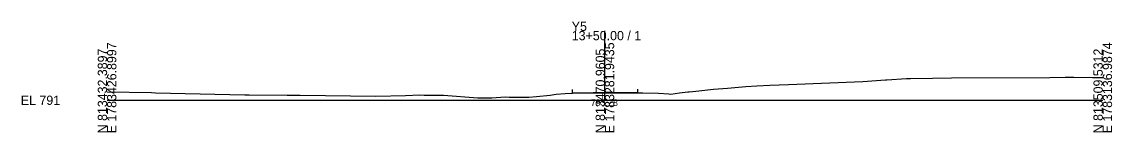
# Model space of a CAD drawing. Extents: x -26 to 1603, y -10 to 6526.
# Drawn here: x 1274.3 to 1602.8, y 490.3 to 523.7 of the extents above; entities that cross this region are included whole.
import ezdxf

# ---------------------------------------------------------------- set-up
doc = ezdxf.new("R2010")
doc.units = 0
for name, color, linetype in [('Exist Cross Section Cell', 7, 'Continuous'), ('Exist XS Center Line Elevation Label', 7, 'Continuous'), ('Exist XS Ground Line', 7, 'Continuous'), ('Prop XS EOT Tick Mark', 7, 'Continuous'), ('Prop XS Finish Grade Pavement', 7, 'Continuous')]:
    doc.layers.add(name, color=color, linetype=linetype)

msp = doc.modelspace()

# ---------------------------------------------------------------- linework, layer by layer
at = {"layer": 'Exist Cross Section Cell'}
for p, q in [((1450, 500), (1450, 520.95)), ((1300, 500), (1450, 500)), ((1450, 500), (1600, 500))]:
    msp.add_line(p, q, dxfattribs=at)
at = {"layer": 'Exist XS Ground Line'}
for p, q in [((1527.7, 505.7), (1534.55, 506.19)), ((1534.55, 506.19), (1534.91, 506.21)), ((1534.91, 506.21), (1540.91, 506.59)), ((1540.91, 506.59), (1542.07, 506.62)), ((1542.07, 506.62), (1548.73, 506.67)), ((1548.73, 506.67), (1554.42, 506.75)), ((1554.42, 506.75), (1584.03, 506.91)), ((1584.03, 506.91), (1588.69, 506.98)), ((1588.69, 506.98), (1591.33, 506.94)), ((1591.33, 506.94), (1596.88, 506.87)), ((1596.88, 506.87), (1600, 506.92)), ((1475.36, 502.52), (1477.42, 502.73)), ((1477.42, 502.73), (1482.76, 503.31)), ((1482.76, 503.31), (1486.98, 503.65)), ((1486.98, 503.65), (1492.47, 504.14)), ((1492.47, 504.14), (1495.81, 504.31)), ((1495.81, 504.31), (1499.65, 504.51)), ((1499.65, 504.51), (1505.3, 504.8)), ((1505.3, 504.8), (1527.7, 505.7)), ((1300, 502.5), (1313.35, 502.33)), ((1313.35, 502.33), (1314.59, 502.27)), ((1314.59, 502.27), (1336.94, 501.72)), ((1336.94, 501.72), (1341.48, 501.66)), ((1341.48, 501.66), (1342.85, 501.67)), ((1342.85, 501.67), (1354.29, 501.51)), ((1354.29, 501.51), (1358.18, 501.53)), ((1358.18, 501.53), (1381.01, 501.27)), ((1381.01, 501.27), (1389.89, 501.42)), ((1389.89, 501.42), (1394.24, 501.59)), ((1394.24, 501.59), (1395.53, 501.54)), ((1395.53, 501.54), (1401.38, 501.57)), ((1401.38, 501.57), (1411.71, 500.72)), ((1411.71, 500.72), (1413.49, 500.7)), ((1413.49, 500.7), (1415.96, 500.75)), ((1415.96, 500.75), (1419.99, 501.02)), ((1419.99, 501.02), (1421.1, 500.92)), ((1421.1, 500.92), (1422.36, 500.96)), ((1422.36, 500.96), (1427.06, 500.89)), ((1427.06, 500.89), (1429.41, 501.14)), ((1429.41, 501.14), (1433.5, 501.56)), ((1433.5, 501.56), (1435.29, 501.83)), ((1435.29, 501.83), (1437.98, 502.03)), ((1437.98, 502.03), (1440.24, 502.1)), ((1440.24, 502.1), (1446.49, 502.21)), ((1446.49, 502.21), (1449.99, 502.28)), ((1449.99, 502.28), (1451.82, 502.27)), ((1451.82, 502.27), (1459.87, 502.21)), ((1459.87, 502.21), (1461.44, 502.2)), ((1461.44, 502.2), (1466.15, 502.18)), ((1466.15, 502.18), (1469.29, 501.92)), ((1469.29, 501.92), (1469.87, 501.84)), ((1469.87, 501.84), (1472.42, 502.19)), ((1472.42, 502.19), (1474.96, 502.52)), ((1474.96, 502.52), (1475.36, 502.52))]:
    msp.add_line(p, q, dxfattribs=at)
at = {"layer": 'Prop XS EOT Tick Mark'}
for p, q in [((1440.22, 502.22), (1440.22, 503.22)), ((1459.87, 502.33), (1459.87, 503.33))]:
    msp.add_line(p, q, dxfattribs=at)
at = {"layer": 'Prop XS Finish Grade Pavement'}
for p, q in [((1440.22, 502.22), (1440.24, 502.22)), ((1440.24, 502.22), (1446.49, 502.33)), ((1446.49, 502.33), (1449.99, 502.4)), ((1449.99, 502.4), (1451.82, 502.4)), ((1451.82, 502.4), (1459.87, 502.33))]:
    msp.add_line(p, q, dxfattribs=at)

# ---------------------------------------------------------------- texts
at = {"layer": 'Exist Cross Section Cell'}
for s, p in [('Y5', (1440, 520.95)), ('13+50.00 / 1', (1440, 518.15)), ('EL 791', (1274, 498.6))]:
    msp.add_text(s, height=2.8, dxfattribs=at).set_placement(p)
for s, p in [('E 1783426.8997', (1302.8, 490)), ('E 1783281.9435', (1452.8, 490)), ('E 1783136.9874', (1602.8, 490)), ('N 813432.3897', (1300, 490)), ('N 813470.9605', (1450, 490)), ('N 813509.5312', (1600, 490))]:
    msp.add_text(s, height=2.8, rotation=90, dxfattribs=at).set_placement(p)
at = {"layer": 'Exist XS Center Line Elevation Label'}
msp.add_text('793.28', height=2, dxfattribs=at).set_placement((1445.73, 498.28))

doc.saveas('drawing.dxf')
